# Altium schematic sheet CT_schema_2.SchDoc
size 298 x 230 mm
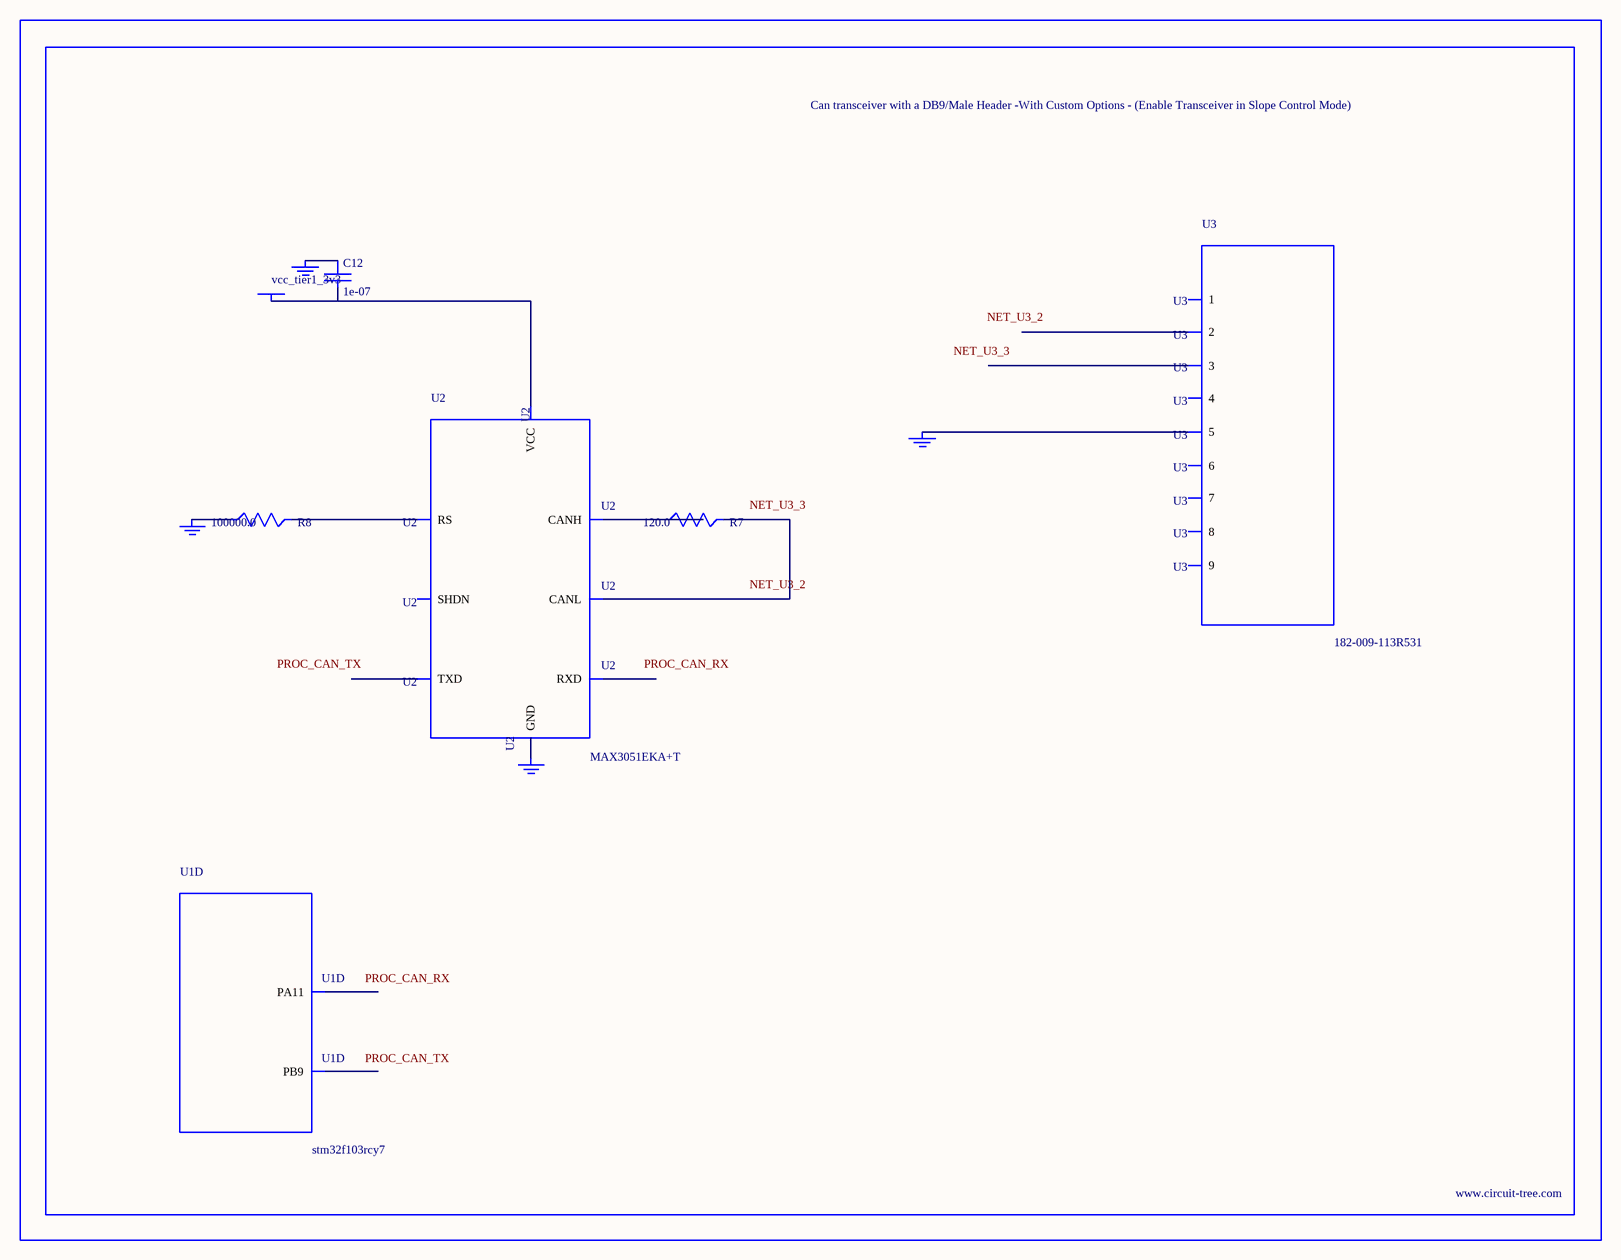
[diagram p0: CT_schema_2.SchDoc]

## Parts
BORDER1  (no value)
C12  1e-07  [C0402]
GND_INSTANCE_1_0  (no value)
GND_INSTANCE_1_1  (no value)
GND_INSTANCE_1_2  (no value)
GND_INSTANCE_1_3  (no value)
POWER_INSTANCE_1_0  vcc_tier1_3v3
R7  120.0  [R0603]
R8  100000.0  [R0603]
U1  stm32f103rcy7  [WLCSP64]  (part D of 7)
U2  MAX3051EKA+T  [SOT-23-8]
U3  182-009-113R531  [182-009-MALE]

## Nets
NetC12_1: C12.1 GND_INSTANCE_1_0.0(GND)
NetC12_2: C12.2 POWER_INSTANCE_1_0.0(PWR) U2.3(VCC)
NetGND_INSTANCE_1_1_0: GND_INSTANCE_1_1.0(GND) R8.1
NetGND_INSTANCE_1_2_0: GND_INSTANCE_1_2.0(GND) U2.2(GND)
NetGND_INSTANCE_1_3_0: GND_INSTANCE_1_3.0(GND) U3.5
NetR7_1: R7.1 U2.7(CANH)
NetR7_2: R7.2 U2.6(CANL)
NetR8_2: R8.2 U2.8(RS)

Not connected (* = marked no-connect by the designer): U1 B6(PB9) C1(PA11); U2 1(TXD) 4(RXD) 5(SHDN); U3 1 2 3 4 6 7 8 9

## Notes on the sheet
- Labels drawn without touching a wire or pin: NET_U3_2, NET_U3_3, PROC_CAN_RX, PROC_CAN_TX

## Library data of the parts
BORDER1 = BORDER_PAGE1
C12 = C0402C104K3RACTU
GND_INSTANCE_1_0-GND_INSTANCE_1_3 = GND
POWER_INSTANCE_1_0 = PWR
R7 = RC0603JR-07120RL
R8 = RC0603JR-07100KL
